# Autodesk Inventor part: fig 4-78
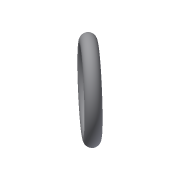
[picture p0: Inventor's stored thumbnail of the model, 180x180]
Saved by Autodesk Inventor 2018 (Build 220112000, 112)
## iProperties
Created: 2012-07
Part Number: fig 4-78
Material: Generic
Document SubType Name: Modeling
Designer: CADCIM
Density: 1 g/cm^3
Appearance: Default
Author: CADCIM
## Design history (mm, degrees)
sketch "Sketch1"
  geometry: L1 (-1.626, -1.876)-(1.626, 1.876); L2 (0, 0)-(7.504, -6.505); C1 r 1.845 at (7.504, -6.505)
  constraints: 4 end point, 1 centre point, 1 midpoint, 1 perpendicular
  dimensions: "d0" = 90 deg dimension on L2.end C1 L1.start L1.end L1 L2.start L2
revolve "Revolution1" sketch "Sketch1" stored, may be unused: angle "d0" = 90 deg
body "Solid1"
